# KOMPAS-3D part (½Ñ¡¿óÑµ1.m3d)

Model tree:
1. Эскиз:1
2. Операция выдавливания:1
     Расстояние 1 = 2.3
3. Эскиз:2
4. Операция выдавливания:2
     Расстояние 1 = 6
5. Эскиз:3
6. Вырезать элемент выдавливания:1
     Расстояние 1 = 1
7. Эскиз:4
8. Операция выдавливания:4
     Расстояние 1 = 1; Расстояние 2 = 1
9. Эскиз:5
10. Вырезать элемент выдавливания:2
     Расстояние 1 = 4
11. Эскиз:6
12. Отверстие:1
13. Эскиз:7
14. Операция выдавливания:5
     Расстояние 1 = 3; Расстояние 2 = 1
15. Эскиз:9
16. Вырезать элемент выдавливания:3
     Расстояние 1 = 7.3
17. Скругление:2
     Радиус = 1
18. Скругление:3
     Радиус = 1
19. Скругление:4
     Радиус = 0.1
20. Скругление:5
     Радиус = 0.1
21. Скругление:7
     Радиус = 0.1
22. Скругление:8
     Радиус = 0.1
23. Массив по концентрической сетке:2  (with: Вырезать элемент выдавливания:3, Скругление:2, Скругление:3)  (labels: Экземпляр ( 1, 1 ); Экземпляр ( 1, 2 ); Экземпляр ( 1, 3 ); Экземпляр ( 1, 4 ))
     N 2 = 5; Шаг 2 = 360
24. Эскиз:12
25. Вырезать элемент выдавливания:4
     Расстояние 1 = 1
26. Скругление:13
     Радиус = 0.2
27. Скругление:14
     Радиус = 0.2
28. Скругление:15
     Радиус = 0.2
29. Скругление:16
     Радиус = 0.2
30. Скругление:17
     Радиус = 0.2
31. Скругление:18
     Радиус = 0.2
32. Массив по концентрической сетке:3  (with: Вырезать элемент выдавливания:4, Скругление:13, Скругление:14, Скругление:15)  (labels: Экземпляр ( 1, 1 ); Экземпляр ( 1, 2 ); Экземпляр ( 1, 3 ); Экземпляр ( 1, 4 ))
     N 2 = 5; Шаг 2 = 360
33. Эскиз:13
34. Операция выдавливания:6
     Расстояние 1 = 1; Расстояние 2 = 1
35. Скругление:19
     Радиус = 1
36. Скругление:20
     Радиус = 0.1
37. Скругление:21
     Радиус = 0.1
38. Массив по концентрической сетке:4  (with: Операция выдавливания:6, Скругление:19, Скругление:20, Скругление:21)  (labels: Экземпляр ( 1, 1 ); Экземпляр ( 1, 2 ); Экземпляр ( 1, 3 ); Экземпляр ( 1, 4 ))
     N 2 = 5; Шаг 2 = 360
39. Массив по концентрической сетке:5  (with: Операция выдавливания:5)  (labels: Экземпляр ( 1, 1 ); Экземпляр ( 1, 2 ); Экземпляр ( 1, 3 ); Экземпляр ( 1, 4 ))
     N 2 = 5; Шаг 2 = 360
40. Эскиз:14
41. Вырезать элемент выдавливания:5
     Расстояние 1 = 2
42. Скругление:22
     Радиус = 2

Referenced files in C:\Program Files\ASCON\KOMPAS-3D V13 Home\Sys\: holelib.lfr
Referenced files in C:\Program Files\ASCON\KOMPAS-3D V12\Sys\: holelib.lfr
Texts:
  Сплав АЛ8  ГОСТ 1583-93
  Отверстие 01
  (вариант 1)
  Номер 1
  Номер 2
